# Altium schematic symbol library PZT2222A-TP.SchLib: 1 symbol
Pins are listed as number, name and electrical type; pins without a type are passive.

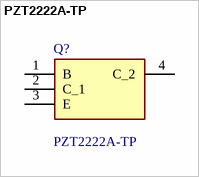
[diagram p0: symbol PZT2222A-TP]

## PZT2222A-TP
designator Q?
Medium Power Bipolar Transistors; Manufacturer_Name: MCC; Geometry.Height: 1.8mm
footprint SOT230P700X180-4N
pins: 1 B, 2 C_1, 3 E, 4 C_2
